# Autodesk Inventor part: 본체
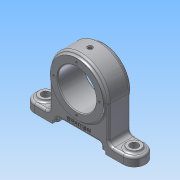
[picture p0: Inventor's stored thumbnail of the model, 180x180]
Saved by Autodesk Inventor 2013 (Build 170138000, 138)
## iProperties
Created: 2019-05
Part Number: 본체
Material: 알루미늄 6061
Document SubType Name: Modeling
Designer: Administrator
Density: 2.71 g/cm^3
Mass: 456.712 g
Surface Area: 318.708 cm^2
Volume: 168.528 cm^3
Author: Administrator
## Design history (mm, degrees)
sketch "스케치1"
  geometry: L1 (-40, 0)-(-40, -48); L2 (-75, -48)-(75, -48); L3 (75, -48)-(75, -60); L4 (75, -60)-(-75, -60); L5 (-75, -60)-(-75, -48); L6 (40, 0)-(40, -48); C1 r 26 at (0, 0); A1 r 40 centre (0, 0) between (40, 0) and (-40, 0); 2 further points
  constraints: 12 end point, 3 parallel, 2 centre point, 2 coincident, 2 point on circle, 2 point on line, 2 tangent, 1 horizontal, 1 midpoint, 1 perpendicular, 1 vertical, 1 vertical alignment
  dimensions: "d0" = 80 diameter of A1; "d2" = 150 distance of L3.end L4.end; "d3" = 60 distance from line of L4 point (0, 0); "d4" = 12 distance of L2.end L3.end; "d5" = 52 diameter of C1
extrude "돌출1" new body sketch "스케치1" stored distance "d6" = 30; taper "d7" = 0 deg
sketch "스케치2"
  geometry: C1 r 26 at (0, 0) reference; C2 r 36 at (0, 0); A1 r 40 centre (0, 0) between (40, 0) and (-40, 0) reference
  constraints: 1 centre point, 1 coincident
  dimensions: "d8" = 72 diameter of C2
extrude "돌출2" join sketch "스케치2" distance "d10" = 3; taper "d11" = 0 deg
sketch "스케치3"
  geometry: C1 r 26 at (0, 0) reference; C2 r 36 at (0, 0); A1 r 40 centre (0, 0) between (40, 0) and (-40, 0) reference
  constraints: 1 centre point, 1 coincident
  dimensions: "d12" = 72 diameter of C2
extrude "돌출3" join sketch "스케치3" distance "d13" = 3; taper "d14" = 0 deg
sketch "스케치4"
  geometry: C1 r 26 at (0, 0) reference; 1 further point
  constraints: 1 vertical alignment
  dimensions: "d15" = 31 distance of point (0, 31) C1.centre
hole "구멍1" sketch "스케치4" at (0, 31) diameter "d16" = 3.242; stored, may be unused: countersink angle "d20" = 90 deg, drill point angle "d22" = 118 deg; dims "d17" = 6, "d18" = 4, "d19" = 2, "d21" = 8
fillet "모깎기1" dims "d26" = 15
sketch "스케치5"
  geometry: C1 r 9 at (20, 15); A1 r 15 centre (20, 15) between (20, 0) and (20, 30) reference; 1 further point
  constraints: 1 centre point, 1 coincident
  dimensions: "d27" = 18 diameter of C1
extrude "돌출4" join sketch "스케치5" distance "d28" = 3; taper "d29" = 0 deg
sketch "스케치6"
  geometry: C1 r 9 at (0, 0) reference; C2 r 5.5 at (0, 0); 1 further point
  constraints: 1 centre point, 1 coincident
  dimensions: "d30" = 11 diameter of C2
extrude "돌출5" cut sketch "스케치6" stored distance "d31" = 3; taper "d32" = 0 deg
sketch "스케치7"
  geometry: C1 r 1.5 at (0, 26); 1 further point
  constraints: 2 vertical alignment, 1 centre point, 1 other
  dimensions: "d33" = 3 diameter of C1
extrude "돌출6" cut sketch "스케치7" stored distance "d34" = 3; taper "d35" = 0 deg
fillet "모깎기2" dims "d36" = 6
sketch "스케치8"
  geometry: L1 (-60, -60)-(60, -60) reference; L2 (-30, -50)-(30, -50); L3 (30, -50)-(30, -60); L4 (30, -60)-(-30, -60); L5 (-30, -60)-(-30, -50); L6 (-36, -56)-(36, -56); L7 (36, -56)-(36, -60); L8 (36, -60)-(-36, -60); L9 (-36, -60)-(-36, -56); C1 r 36 at (0, 0) reference; A1 r 40 centre (0, 0) between (40, 0) and (-40, 0) reference; 2 further points
  constraints: 16 end point, 4 parallel, 2 collinear, 2 horizontal, 2 midpoint, 2 perpendicular, 2 vertical alignment
  dimensions: "d37" = 60 distance of L3.end L4.end; "d39" = 72 distance of L7.end L8.end; "d40" = 10 distance of L2.end L3.end; "d41" = 4 distance of L6.end L7.end
extrude "돌출7" cut sketch "스케치8" stored distance "d42" = 3; taper "d43" = 0 deg
node "작업 평면1"
sketch "스케치9"
  geometry: C1 r 3.5 at (0, 0); 1 further point
  constraints: 1 centre point, 1 coincident
  dimensions: "d45" = 7 diameter of C1
extrude "돌출8" cut sketch "스케치9" distance "d46" = 1; taper "d47" = 0 deg
node "작업 평면5"
sketch "스케치10"
  geometry: C1 r 1 at (0, 0); 1 further point
  constraints: 1 centre point, 1 coincident
  dimensions: "d61" = 2 diameter of C1
extrude "돌출9" cut sketch "스케치10" stored distance "d62" = 1; taper "d63" = 0 deg
node "작업 평면6"
sketch "스케치11"
  geometry: 2 further points
  constraints: 1 coincident
hole "구멍3" sketch "스케치11" at (0, 0) diameter "d65" = 4.917; stored, may be unused: countersink angle "d69" = 90 deg, drill point angle "d71" = 118 deg; dims "d66" = 8, "d67" = 4, "d68" = 2, "d70" = 10
fillet "모깎기3" dims "d72" = 3
fillet "모깎기4" dims "d77" = 3
chamfer "모따기1" distance "d78" = 1; stored, may be unused: second distance "d79" = 2, angle "d80" = 45 deg
fillet "모깎기5" dims "d81" = 3
fillet "모깎기7" dims "d83" = 3
fillet "모깎기8" dims "d84" = 3
sketch "스케치13"
  geometry: L1 (-27, -50)-(27, -50) reference; A1 r 39 centre (0, 0) between (-37, -12.329) and (37, -12.329) reference; 1 further point
  constraints: 1 vertical alignment, 1 other
  dimensions: "d85" = 7 distance from line of point (0, -43) L1
feature "엠보싱1" sketch "스케치13" dims "d0" = 80, "d2" = 150, "d3" = 60, "d4" = 12, "d5" = 52, "d86" = 0.5, "d87" = 0
node "솔리드1"
pattern_circular "원형 패턴1" dims angle "d24" = 360 deg
mirror "대칭1"
mirror "대칭2"
other parameters: "d60" = 26
